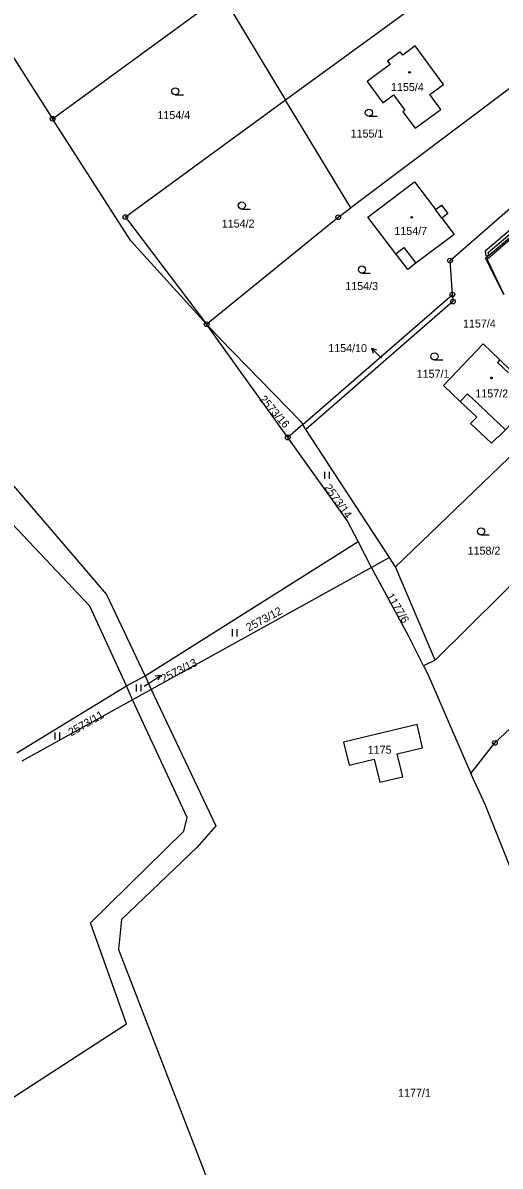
# Model space of a CAD drawing. Extents: x -562167 to -556918, y -1077891 to -1070763.
# Drawn here: x -559528.9 to -559427.6, y -1074790.1 to -1074547.2 of the extents above; entities that cross this region are included whole.
import ezdxf

# ---------------------------------------------------------------- set-up
doc = ezdxf.new("R2010")
doc.units = 0
for name, color, linetype in [('Hranice parcel', 7, 'Continuous'), ('Parcelní čísla', 7, 'Continuous'), ('Pop  PČ popisy', 7, 'Continuous'), ('Vnitřní kresba', 7, 'Continuous'), ('Věcná břemena k části', 7, 'Continuous'), ('Značky bodu BP', 7, 'Continuous'), ('Značky budov', 7, 'Continuous'), ('Značky kultur', 7, 'Continuous')]:
    doc.layers.add(name, color=color, linetype=linetype)

msp = doc.modelspace()

# ---------------------------------------------------------------- linework, layer by layer
at = {"layer": 'Hranice parcel'}
for p, q in [((-559433.14, -1074534.36), (-559473.18, -1074563.64)), ((-559522.64, -1074567.61), (-559482, -1074537.89)), ((-559534.93, -1074548.39), (-559522.64, -1074567.61)), ((-559423.75, -1074559.76), (-559459.33, -1074586.53)), ((-559459.33, -1074586.53), (-559473.18, -1074563.64)), ((-559469.55, -1074632.59), (-559437.77, -1074604.97)), ((-559437.77, -1074604.97), (-559437.67, -1074606.47)), ((-559437.67, -1074606.47), (-559468.89, -1074633.61)), ((-559472.71, -1074635.34), (-559489.93, -1074611.27)), ((-559449.87, -1074662.79), (-559408.79, -1074623.27)), ((-559470.02, -1074631.87), (-559469.55, -1074632.59)), ((-559469.55, -1074632.59), (-559472.71, -1074635.34)), ((-559468.89, -1074633.61), (-559469.55, -1074632.59)), ((-559451.15, -1074660.86), (-559468.89, -1074633.61)), ((-559460.11, -1074652.95), (-559472.71, -1074635.34)), ((-559457.74, -1074657.47), (-559460.11, -1074652.95)), ((-559503, -1074685.96), (-559457.74, -1074657.47)), ((-559454.91, -1074662.95), (-559457.74, -1074657.47)), ((-559451.15, -1074660.86), (-559454.91, -1074662.95)), ((-559449.87, -1074662.79), (-559451.15, -1074660.86)), ((-559454.91, -1074662.95), (-559501.7, -1074688.9)), ((-559441.43, -1074682.68), (-559449.87, -1074662.79)), ((-559441.43, -1074682.68), (-559443.87, -1074683.88)), ((-559506.95, -1074688.08), (-559503, -1074685.96)), ((-559503, -1074685.96), (-559501.7, -1074688.9)), ((-559530.23, -1074702.33), (-559506.95, -1074688.08)), ((-559505.67, -1074691.11), (-559506.95, -1074688.08)), ((-559428.73, -1074700.22), (-559414.71, -1074686.93)), ((-559501.7, -1074688.9), (-559505.67, -1074691.11)), ((-559505.67, -1074691.11), (-559529.16, -1074704.14)), ((-559433.82, -1074706.73), (-559428.73, -1074700.22))]:
    msp.add_line(p, q, dxfattribs=at)
for points in [[(-559503, -1074685.96), (-559511.17, -1074668.62), (-559533.8, -1074642.22), (-559567.59, -1074618.78), (-559593.45, -1074600.06), (-559613.66, -1074584.8), (-559634.82, -1074567.06), (-559641.03, -1074557.13), (-559653.65, -1074535.71), (-559663.06, -1074518.96), (-559671.75, -1074493.51), (-559678.27, -1074473.65), (-559693.99, -1074442.1), (-559705.78, -1074416.35), (-559724.81, -1074374.04), (-559735.98, -1074354.59), (-559754.78, -1074320.67)], [(-559444.45, -1074521.82), (-559484.59, -1074544.79), (-559473.18, -1074563.64)], [(-559455.85, -1074559.69), (-559452.5, -1074564.21), (-559450.27, -1074562.55), (-559447.85, -1074565.83), (-559448.26, -1074566.13), (-559445.65, -1074569.65), (-559440.25, -1074565.62), (-559442.56, -1074562.5), (-559439.64, -1074560.35), (-559445.67, -1074552.14), (-559448.31, -1074554.08), (-559448.85, -1074553.38), (-559451.51, -1074555.36), (-559450.99, -1074556.06), (-559453.63, -1074558.04), (-559455.85, -1074559.69)], [(-559473.18, -1074563.64), (-559507.18, -1074588.51), (-559489.93, -1074611.27)], [(-559506.95, -1074688.08), (-559514.71, -1074671.19), (-559534.85, -1074649.92), (-559572.59, -1074625.7), (-559618.91, -1074589.66), (-559638.44, -1074571.61), (-559672.97, -1074568.51), (-559685.4, -1074573.78)], [(-559489.93, -1074611.27), (-559506.03, -1074593.59), (-559522.64, -1074567.61)], [(-559437.77, -1074604.97), (-559438.26, -1074597.74), (-559416.08, -1074578.43), (-559415.17, -1074574.95)], [(-559440.09, -1074585.97), (-559438.76, -1074587.77), (-559440, -1074588.75), (-559437.41, -1074592.2), (-559445.54, -1074598.33), (-559447.26, -1074599.62), (-559449.81, -1074596.29), (-559455.75, -1074588.54), (-559445.79, -1074581.03), (-559441.37, -1074586.93), (-559440.09, -1074585.97)], [(-559426.82, -1074604.93), (-559430.72, -1074597.23), (-559414.59, -1074583.53), (-559413.89, -1074583.15)], [(-559413.89, -1074583.15), (-559430.37, -1074597.5), (-559426.82, -1074604.93)], [(-559489.93, -1074611.27), (-559461.99, -1074588.53), (-559459.33, -1074586.53)], [(-559489.93, -1074611.27), (-559487.13, -1074614.34), (-559470.02, -1074631.87)], [(-559432.58, -1074631), (-559436.1, -1074627.68), (-559439.64, -1074624.31), (-559431.23, -1074615.45), (-559427.67, -1074618.85), (-559425.33, -1074621.08), (-559419.67, -1074626.5), (-559426.52, -1074633.68), (-559428.04, -1074635.28), (-559428.13, -1074635.2), (-559429.46, -1074636.57), (-559433.9, -1074632.38), (-559432.58, -1074631)], [(-559384.79, -1074627.09), (-559413.15, -1074654.63), (-559441.43, -1074682.68)], [(-559443.87, -1074683.88), (-559447.1, -1074677.51), (-559454.91, -1074662.95)], [(-559443.87, -1074683.88), (-559442.98, -1074685.65), (-559433.82, -1074706.73)], [(-559501.7, -1074688.9), (-559487.95, -1074717.88), (-559491.97, -1074722.41), (-559508.01, -1074737.76), (-559508.63, -1074744.1), (-559490.55, -1074791.1), (-559481.41, -1074814.96)], [(-559547.69, -1074786.16), (-559545.27, -1074784.76), (-559506.94, -1074759.94), (-559514.58, -1074738.42), (-559494.75, -1074718.98), (-559494.04, -1074716.08), (-559505.67, -1074691.11)], [(-559445.27, -1074696.3), (-559460.87, -1074700.05), (-559459.71, -1074704.95), (-559454.36, -1074703.68), (-559453.19, -1074708.59), (-559448.32, -1074707.41), (-559449.48, -1074702.52), (-559444.09, -1074701.24), (-559445.27, -1074696.3)], [(-559421.4, -1074736.87), (-559430.8, -1074713.29), (-559433.82, -1074706.73)]]:
    msp.add_lwpolyline(points, dxfattribs=at)
at = {"layer": 'Pop  PČ popisy'}
for p, q in [((-559452.82, -1074618.47), (-559454.94, -1074616.35)), ((-559454.94, -1074616.35), (-559453.88, -1074616.7)), ((-559454.94, -1074616.35), (-559454.59, -1074617.41)), ((-559502.26, -1074687.57), (-559499.74, -1074685.94)), ((-559499.74, -1074685.94), (-559500.86, -1074686.06)), ((-559499.74, -1074685.94), (-559500.31, -1074686.9)), ((-559503.21, -1074688.2), (-559502.26, -1074687.57))]:
    msp.add_line(p, q, dxfattribs=at)
at = {"layer": 'Vnitřní kresba'}
for p, q in [((-559440, -1074588.75), (-559441.37, -1074586.93)), ((-559449.81, -1074596.29), (-559448.06, -1074594.96)), ((-559448.06, -1074594.96), (-559445.54, -1074598.33)), ((-559427.67, -1074618.85), (-559428.19, -1074619.4)), ((-559428.19, -1074619.4), (-559425.86, -1074621.62)), ((-559436.1, -1074627.68), (-559434.54, -1074626.08)), ((-559434.54, -1074626.08), (-559426.52, -1074633.68))]:
    msp.add_line(p, q, dxfattribs=at)
at = {"layer": 'Věcná břemena k části'}
msp.add_lwpolyline([(-559411.78, -1074580.94), (-559412.08, -1074580.41), (-559417.51, -1074584.52), (-559430.82, -1074595.78), (-559430.65, -1074596.71), (-559430.06, -1074596.6), (-559430.16, -1074596.02), (-559417.13, -1074584.98)], close=True, dxfattribs=at)
at = {"layer": 'Značky bodu BP'}
for centre, radius in [((-559522.64, -1074567.61), 0.5), ((-559522.64, -1074567.61), 0.0303), ((-559507.18, -1074588.51), 0.5), ((-559507.18, -1074588.51), 0.0303), ((-559461.99, -1074588.53), 0.5), ((-559461.99, -1074588.53), 0.0303), ((-559438.26, -1074597.74), 0.5), ((-559438.26, -1074597.74), 0.0303), ((-559437.77, -1074604.97), 0.5), ((-559437.77, -1074604.97), 0.0303), ((-559437.67, -1074606.47), 0.5), ((-559437.67, -1074606.47), 0.0303), ((-559489.93, -1074611.27), 0.5), ((-559489.93, -1074611.27), 0.0303), ((-559472.71, -1074635.34), 0.5), ((-559472.71, -1074635.34), 0.0303), ((-559428.73, -1074700.22), 0.5), ((-559428.73, -1074700.22), 0.0303)]:
    msp.add_circle(centre, radius, dxfattribs=at)
at = {"layer": 'Značky budov'}
for centre in [(-559446.86, -1074557.76), (-559446.41, -1074588.57), (-559429.47, -1074622.68)]:
    msp.add_circle(centre, 0.175, dxfattribs=at)
at = {"layer": 'Značky kultur'}
for p, q in [((-559496.6, -1074562.53), (-559494.85, -1074562.53)), ((-559455.5, -1074567.08), (-559453.75, -1074567.08)), ((-559482.47, -1074586.8), (-559480.72, -1074586.8)), ((-559456.97, -1074600.4), (-559455.22, -1074600.4)), ((-559441.57, -1074618.87), (-559439.82, -1074618.87)), ((-559464.86, -1074644.12), (-559464.86, -1074642.62)), ((-559463.86, -1074644.12), (-559463.86, -1074642.62)), ((-559431.68, -1074656.05), (-559429.93, -1074656.05)), ((-559484.45, -1074677.59), (-559484.45, -1074676.09)), ((-559483.45, -1074677.59), (-559483.45, -1074676.09)), ((-559504.82, -1074689.33), (-559504.82, -1074687.83)), ((-559503.82, -1074689.33), (-559503.82, -1074687.83)), ((-559522.09, -1074699.48), (-559522.09, -1074697.98)), ((-559521.09, -1074699.48), (-559521.09, -1074697.98))]:
    msp.add_line(p, q, dxfattribs=at)
for centre in [(-559496.6, -1074561.78), (-559455.5, -1074566.33), (-559482.47, -1074586.05), (-559456.97, -1074599.65), (-559441.57, -1074618.12), (-559431.68, -1074655.3)]:
    msp.add_circle(centre, 0.75, dxfattribs=at)

# ---------------------------------------------------------------- texts
at = {"layer": 'Parcelní čísla'}
for s, p in [('1155/4', (-559450.8, -1074561.73)), ('1154/4', (-559500.38, -1074567.69)), ('1155/1', (-559459.37, -1074571.61)), ('1154/2', (-559486.72, -1074590.74)), ('1154/7', (-559450.08, -1074592.3)), ('1154/3', (-559460.51, -1074604.01)), ('1157/4', (-559435.51, -1074611.97)), ('1154/10', (-559464.12, -1074617.19)), ('1157/1', (-559445.35, -1074622.66)), ('1157/2', (-559432.89, -1074626.84)), ('1158/2', (-559434.54, -1074660.24)), ('1175', (-559455.75, -1074702.53)), ('1177/1', (-559449.29, -1074775.42))]:
    msp.add_text(s, height=1.7, dxfattribs=at).set_placement(p)
for s, rotation, p in [('2573/16', 311, (-559478.84, -1074627.3)), ('2573/14', 305, (-559465.05, -1074645.96)), ('1177/6', 301, (-559451.86, -1074669.02)), ('2573/12', 28, (-559481.01, -1074676.59)), ('2573/13', 27, (-559499.11, -1074687.45)), ('2573/11', 30, (-559518.69, -1074698.86))]:
    msp.add_text(s, height=1.7, rotation=rotation, dxfattribs=at).set_placement(p)

doc.saveas('drawing.dxf')
